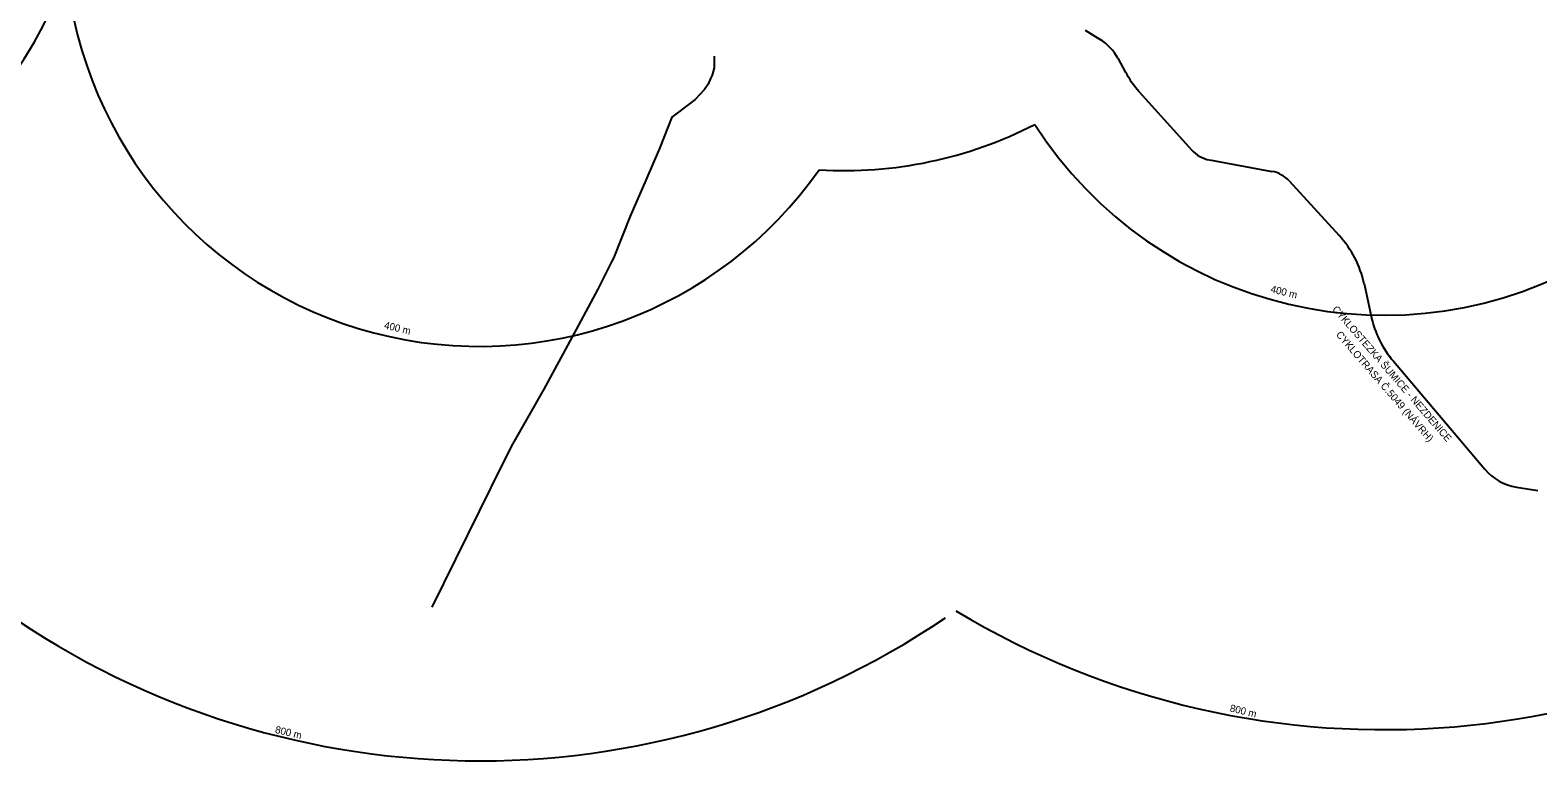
# Model space of a CAD drawing. Extents: x -520790 to -517278, y -1190021 to -1185077.
# Drawn here: x -519555 to -518101, y -1188146 to -1187441 of the extents above; entities that cross this region are included whole.
import ezdxf

# ---------------------------------------------------------------- set-up
doc = ezdxf.new("R2010")
doc.units = 0
for name, color, linetype in [('cyklostezka_s', 7, 'Continuous'), ('dostupnost_s', 7, 'Continuous'), ('stezka_s', 7, 'Continuous')]:
    doc.layers.add(name, color=color, linetype=linetype)

msp = doc.modelspace()

# ---------------------------------------------------------------- linework, layer by layer
at = {"layer": 'cyklostezka_s'}
for p, q in [((-518537.9, -1187440.6), (-518523.5, -1187449.7)), ((-518506.5, -1187467.8), (-518498.9, -1187481.5)), ((-518485.8, -1187500), (-518435.1, -1187556.4)), ((-518418.2, -1187565.9), (-518357.9, -1187576.9)), ((-518341.2, -1187586.2), (-518293, -1187638.8)), ((-518268.9, -1187685.2), (-518262.1, -1187716.8)), ((-518240.7, -1187760.2), (-518152.5, -1187864.5)), ((-518121.9, -1187881.6), (-518101.4, -1187884.8))]:
    msp.add_line(p, q, dxfattribs=at)
for centre, radius, start, end in [((-518550.2, -1187491.9), 50, 28.9162, 57.6942), ((-518411.3, -1187433.2), 100, 208.9163, 221.8979), ((-518412.8, -1187536.4), 30, 221.896, 259.5919), ((-518363.3, -1187606.4), 30, 42.5202, 79.5933), ((-518366.7, -1187706.4), 100, 12.2147, 42.5202), ((-518164.4, -1187695.6), 100, 192.2137, 220.234), ((-518114.3, -1187832.2), 50, 220.2323, 261.2546)]:
    msp.add_arc(centre, radius, start, end, dxfattribs=at)
at = {"layer": 'dostupnost_s'}
for centre, radius, start, end in [((-519897.8, -1187252.1), 800, 53.8723, 292.3308), ((-518249.8, -1187315.8), 800, 238.9173, 94.6412), ((-519897.8, -1187252.1), 400, 5.5181, 340.685), ((-518249.8, -1187315.8), 400, 212.6563, 117.2847), ((-519122.2, -1187345.9), 400, 185.5181, 324.9976), ((-518770, -1187176.1), 400, 266.4804, 297.2847), ((-519122.2, -1187345.9), 800, 233.8723, 304.1795)]:
    msp.add_arc(centre, radius, start, end, dxfattribs=at)
at = {"layer": 'stezka_s'}
msp.add_lwpolyline([(-518895.8, -1187465.7), (-518895.8, -1187477), (-518897.6, -1187484.2), (-518899.4, -1187487.4), (-518901.4, -1187492.8), (-518905, -1187497.8), (-518909.8, -1187503.2), (-518914.2, -1187507.6), (-518918.4, -1187510.9), (-518936.5, -1187524.6), (-518948.6, -1187554.7), (-518961.8, -1187585.5), (-518976.9, -1187620.3), (-518993, -1187660.6), (-518994.5, -1187663.7), (-519008, -1187690.5), (-519028.7, -1187729.6), (-519059.9, -1187787), (-519090.4, -1187840.3), (-519099.7, -1187858.6), (-519168, -1187997.5)], dxfattribs=at)

# ---------------------------------------------------------------- texts
at = {"layer": 'cyklostezka_s'}
for s, p in [('CYKLOSTEZKA ŠUMICE - NEZDENICE', (-518300.1, -1187710.4)), ('CYKLOTRASA Č.5049 (NÁVRH)', (-518296.5, -1187734.8))]:
    msp.add_text(s, height=7, rotation=310.8634, dxfattribs=at).set_placement(p)
at = {"layer": 'dostupnost_s'}
for s, p in [('400 m', (-518359.6, -1187693.6)), ('400 m', (-519214.6, -1187728.5)), ('800 m', (-518398.9, -1188098.1)), ('800 m', (-519319.7, -1188118.8))]:
    msp.add_text(s, height=7, rotation=346.4234, dxfattribs=at).set_placement(p)

doc.saveas('drawing.dxf')
